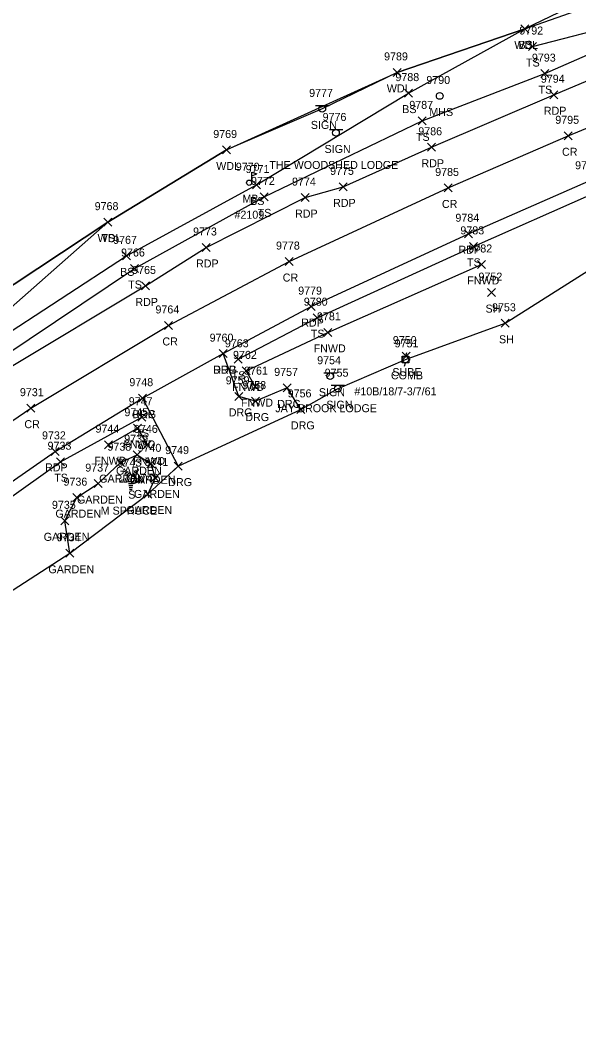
# Model space of a CAD drawing. Extents: x 1651685 to 1653558, y 889533 to 891085.
# Drawn here: x 1651859.6 to 1651999.4, y 889537.9 to 889789.1 of the extents above; entities that cross this region are included whole.
import ezdxf

# ---------------------------------------------------------------- set-up
doc = ezdxf.new("R2010")
doc.units = 0
for name, color, linetype in [('L_A', 7, 'Continuous'), ('L_C', 7, 'Continuous'), ('L_I', 7, 'Continuous'), ('L_TIC', 7, 'Continuous'), ('LAPB', 7, 'Continuous'), ('LAWA', 7, 'Continuous'), ('LELB', 7, 'Continuous'), ('LFNC', 7, 'Continuous'), ('LMB', 7, 'Continuous'), ('LSOGP', 7, 'Continuous'), ('LTC', 7, 'Continuous'), ('P_A', 7, 'Continuous'), ('P_I', 7, 'Continuous'), ('P_TIC', 7, 'Continuous'), ('PET', 7, 'Continuous'), ('PRC', 7, 'Continuous'), ('R_A', 7, 'Continuous'), ('R_I', 7, 'Continuous'), ('R_TIC', 7, 'Continuous'), ('RDG', 7, 'Continuous'), ('S_A', 7, 'Continuous'), ('S_C', 7, 'Continuous'), ('S_I', 7, 'Continuous'), ('SSGN', 7, 'Continuous'), ('U_A', 7, 'Continuous'), ('U_C', 7, 'Continuous'), ('U_I', 7, 'Continuous'), ('U_TIC', 7, 'Continuous'), ('UP', 7, 'Continuous'), ('USMH', 7, 'Continuous')]:
    doc.layers.add(name, color=color, linetype=linetype)

msp = doc.modelspace()

# ---------------------------------------------------------------- linework, layer by layer
at = {"layer": 'L_TIC'}
for points in [[(1651984.79, 889785.86), (1651986.79, 889787.86)], [(1651986.79, 889785.86), (1651984.79, 889787.86)], [(1651984.79, 889785.86), (1651986.79, 889787.86)], [(1651986.79, 889785.86), (1651984.79, 889787.86)], [(1651986.72, 889781.44), (1651988.72, 889783.44)], [(1651988.72, 889781.44), (1651986.72, 889783.44)], [(1651952.91, 889774.98), (1651954.91, 889776.98)], [(1651954.91, 889774.98), (1651952.91, 889776.98)], [(1651989.86, 889774.67), (1651991.86, 889776.67)], [(1651991.86, 889774.67), (1651989.86, 889776.67)], [(1651955.73, 889769.8), (1651957.73, 889771.8)], [(1651957.73, 889769.8), (1651955.73, 889771.8)], [(1651959.2, 889762.86), (1651961.2, 889764.86)], [(1651961.2, 889762.86), (1651959.2, 889764.86)], [(1651910.24, 889755.58), (1651912.24, 889757.58)], [(1651912.24, 889755.58), (1651910.24, 889757.58)], [(1651917.71, 889746.83), (1651919.71, 889748.83)], [(1651919.71, 889746.83), (1651917.71, 889748.83)], [(1651919.63, 889743.86), (1651921.63, 889745.86)], [(1651921.63, 889743.86), (1651919.63, 889745.86)], [(1651880.58, 889737.54), (1651882.58, 889739.54)], [(1651882.58, 889737.54), (1651880.58, 889739.54)], [(1651880.58, 889737.54), (1651882.58, 889739.54)], [(1651882.58, 889737.54), (1651880.58, 889739.54)], [(1651971.97, 889731.49), (1651973.97, 889733.49)], [(1651973.97, 889731.49), (1651971.97, 889733.49)], [(1651885.2, 889729.12), (1651887.2, 889731.12)], [(1651887.2, 889729.12), (1651885.2, 889731.12)], [(1651887.23, 889725.95), (1651889.23, 889727.95)], [(1651889.23, 889725.95), (1651887.23, 889727.95)], [(1651973.98, 889726.96), (1651975.98, 889728.96)], [(1651975.98, 889726.96), (1651973.98, 889728.96)], [(1651976.51, 889719.93), (1651978.51, 889721.93)], [(1651978.51, 889719.93), (1651976.51, 889721.93)], [(1651932.92, 889713.66), (1651934.92, 889715.66)], [(1651934.92, 889713.66), (1651932.92, 889715.66)], [(1651979.89, 889712.26), (1651981.89, 889714.26)], [(1651981.89, 889712.26), (1651979.89, 889714.26)], [(1651935.55, 889709.99), (1651937.55, 889711.99)], [(1651937.55, 889709.99), (1651935.55, 889711.99)], [(1651913.13, 889703.26), (1651915.13, 889705.26)], [(1651915.13, 889703.26), (1651913.13, 889705.26)], [(1651915.17, 889700.36), (1651917.17, 889702.36)], [(1651917.17, 889700.36), (1651915.17, 889702.36)], [(1651917.38, 889696.42), (1651919.38, 889698.42)], [(1651919.38, 889696.42), (1651917.38, 889698.42)], [(1651889.05, 889688.78), (1651891.05, 889690.78)], [(1651891.05, 889688.78), (1651889.05, 889690.78)], [(1651887.97, 889686.04), (1651889.97, 889688.04)], [(1651889.97, 889686.04), (1651887.97, 889688.04)], [(1651880.74, 889681.91), (1651882.74, 889683.91)], [(1651882.74, 889681.91), (1651880.74, 889683.91)], [(1651890.42, 889681.85), (1651892.42, 889683.85)], [(1651892.42, 889681.85), (1651890.42, 889683.85)], [(1651887.94, 889679.41), (1651889.94, 889681.41)], [(1651889.94, 889679.41), (1651887.94, 889681.41)], [(1651868.76, 889677.65), (1651870.76, 889679.65)], [(1651870.76, 889677.65), (1651868.76, 889679.65)], [(1651883.73, 889677.42), (1651885.73, 889679.42)], [(1651885.73, 889677.42), (1651883.73, 889679.42)], [(1651891.34, 889677.13), (1651893.34, 889679.13)], [(1651893.34, 889677.13), (1651891.34, 889679.13)], [(1651878.18, 889672.18), (1651880.18, 889674.18)], [(1651880.18, 889672.18), (1651878.18, 889674.18)], [(1651892.43, 889673.6), (1651894.43, 889675.6)], [(1651894.43, 889673.6), (1651892.43, 889675.6)], [(1651890.54, 889669.58), (1651892.54, 889671.58)], [(1651892.54, 889669.58), (1651890.54, 889671.58)], [(1651872.8, 889668.67), (1651874.8, 889670.67)], [(1651874.8, 889668.67), (1651872.8, 889670.67)], [(1651869.85, 889662.88), (1651871.85, 889664.88)], [(1651871.85, 889662.88), (1651869.85, 889664.88)], [(1651871.04, 889654.76), (1651873.04, 889656.76)], [(1651873.04, 889654.76), (1651871.04, 889656.76)]]:
    msp.add_lwpolyline(points, dxfattribs=at)
at = {"layer": 'LAPB'}
msp.add_lwpolyline([(1651872.04, 889655.76), (1651870.85, 889663.88), (1651873.8, 889669.67), (1651879.18, 889673.18), (1651884.73, 889678.42), (1651888.94, 889680.41), (1651892.34, 889678.13), (1651893.43, 889674.6), (1651891.54, 889670.58)], dxfattribs=at)
at = {"layer": 'LAWA'}
msp.add_lwpolyline([(1651786.37, 889684.82), (1651812.33, 889694.08), (1651846.44, 889715.35), (1651881.58, 889738.54), (1651911.24, 889756.58), (1651953.91, 889775.98), (1651985.79, 889786.86)], dxfattribs=at)
at = {"layer": 'LELB'}
for points in [[(1651783.6, 889675.23), (1651805.26, 889676.92), (1651818.09, 889682.86), (1651843.19, 889699.23), (1651855.35, 889704.9), (1651888.23, 889726.95), (1651920.63, 889744.86), (1651960.2, 889763.86), (1651990.86, 889775.67), (1652032.94, 889794.22), (1652064, 889805.11), (1652064.62, 889808.53), (1652063.28, 889810.56), (1652051.23, 889809.28), (1652039.29, 889812.4)], [(1651845.19, 889705.05), (1651852.98, 889708.46), (1651886.2, 889730.12), (1651918.71, 889747.83), (1651956.73, 889770.8), (1651985.79, 889786.86), (1652029.06, 889802.11), (1652062.87, 889807.04)], [(1651987.72, 889782.44), (1652032.94, 889794.22)], [(1651914.13, 889704.26), (1651933.92, 889714.66), (1651972.97, 889732.49), (1652002.78, 889745.6), (1652031.52, 889758.06)], [(1651784.29, 889679.75), (1651801.82, 889681.07), (1651814.94, 889688.3), (1651838.28, 889704.72), (1651850.92, 889711.55), (1651881.58, 889738.54)], [(1651735.5, 889537.87), (1651729.21, 889546.46), (1651724.72, 889554.06), (1651746.88, 889576.56), (1651775.98, 889603.69), (1651804.95, 889630.07), (1651836.41, 889654.97), (1651869.76, 889678.65), (1651890.05, 889689.78)]]:
    msp.add_lwpolyline(points, dxfattribs=at)
at = {"layer": 'LFNC'}
for points in [[(1651918.38, 889697.42), (1651916.17, 889701.36), (1651936.55, 889710.99), (1651974.98, 889727.96)], [(1651881.74, 889682.91), (1651888.97, 889687.04), (1651891.42, 889682.85)]]:
    msp.add_lwpolyline(points, dxfattribs=at)
at = {"layer": 'LMB'}
for p, q in [((1651917.56, 889748.41), (1651917.56, 889751.01)), ((1651917.56, 889751), (1651918.85, 889750.62)), ((1651917.56, 889750.11), (1651918.85, 889750.61)), ((1651916.91, 889748.4), (1651916.91, 889748.4))]:
    msp.add_line(p, q, dxfattribs=at)
msp.add_circle((1651916.91, 889748.4), 0.656, dxfattribs=at)
at = {"layer": 'LSOGP'}
for points in [[(1652028.35, 889807.39), (1651985.79, 889786.86), (1651953.91, 889775.99), (1651935.16, 889766.85), (1651911.24, 889756.58), (1651881.58, 889738.53), (1651846.44, 889715.35)], [(1651846.48, 889639.3), (1651872.04, 889655.76), (1651891.54, 889670.58), (1651899.18, 889677.56), (1651929.84, 889691.74), (1651939.03, 889696.91), (1651955.96, 889704.24), (1651980.89, 889713.26), (1652008.19, 889730.53)]]:
    msp.add_lwpolyline(points, dxfattribs=at)
at = {"layer": 'LTC'}
for p, q in [((1651885.47, 889676.64), (1651885.82, 889676.9)), ((1651885.68, 889676.18), (1651886.21, 889676.56)), ((1651888.5, 889676.53), (1651889.05, 889676.13)), ((1651888.87, 889676.88), (1651889.29, 889676.58)), ((1651884.5, 889673.92), (1651884.65, 889673.45)), ((1651884.96, 889674.14), (1651885.17, 889673.48)), ((1651885.41, 889674.35), (1651885.68, 889673.52)), ((1651885.87, 889674.57), (1651886.2, 889673.55)), ((1651885.89, 889675.71), (1651886.59, 889676.22)), ((1651886.1, 889675.24), (1651886.98, 889675.88)), ((1651886.32, 889674.79), (1651887.33, 889675.52)), ((1651886.32, 889674.79), (1651886.71, 889673.6)), ((1651887.33, 889675.52), (1651888.33, 889674.8)), ((1651887.75, 889675.84), (1651888.56, 889675.25)), ((1651888.33, 889674.8), (1651887.94, 889673.6)), ((1651888.13, 889676.18), (1651888.8, 889675.69)), ((1651888.77, 889674.53), (1651888.43, 889673.49)), ((1651889.21, 889674.28), (1651888.93, 889673.39)), ((1651889.66, 889674.03), (1651889.42, 889673.3)), ((1651887.94, 889673.6), (1651886.71, 889673.6)), ((1651887.9, 889673.1), (1651886.76, 889673.1)), ((1651887.82, 889672.6), (1651886.83, 889672.6)), ((1651887.73, 889672.1), (1651886.9, 889672.1)), ((1651887.65, 889671.6), (1651886.98, 889671.6)), ((1651890.1, 889673.78), (1651889.92, 889673.2))]:
    msp.add_line(p, q, dxfattribs=at)
at = {"layer": 'P_TIC'}
for points in [[(1651992.09, 889769.39), (1651994.09, 889771.39)], [(1651994.09, 889769.39), (1651992.09, 889771.39)], [(1651995.7, 889759.13), (1651997.7, 889761.13)], [(1651997.7, 889759.13), (1651995.7, 889761.13)], [(1651961.5, 889756.26), (1651963.5, 889758.26)], [(1651963.5, 889756.26), (1651961.5, 889758.26)], [(1651939.4, 889746.37), (1651941.4, 889748.37)], [(1651941.4, 889746.37), (1651939.4, 889748.37)], [(1651965.67, 889746.09), (1651967.67, 889748.09)], [(1651967.67, 889746.09), (1651965.67, 889748.09)], [(1651929.88, 889743.68), (1651931.88, 889745.68)], [(1651931.88, 889743.68), (1651929.88, 889745.68)], [(1651970.73, 889734.64), (1651972.73, 889736.64)], [(1651972.73, 889734.64), (1651970.73, 889736.64)], [(1651905.13, 889731.21), (1651907.13, 889733.21)], [(1651907.13, 889731.21), (1651905.13, 889733.21)], [(1651925.87, 889727.69), (1651927.87, 889729.69)], [(1651927.87, 889727.69), (1651925.87, 889729.69)], [(1651889.95, 889721.59), (1651891.95, 889723.59)], [(1651891.95, 889721.59), (1651889.95, 889723.59)], [(1651931.43, 889716.43), (1651933.43, 889718.43)], [(1651933.43, 889716.43), (1651931.43, 889718.43)], [(1651895.77, 889711.72), (1651897.77, 889713.72)], [(1651897.77, 889711.72), (1651895.77, 889713.72)], [(1651909.42, 889704.67), (1651911.42, 889706.67)], [(1651911.42, 889704.67), (1651909.42, 889706.67)], [(1651889.21, 889693.54), (1651891.21, 889695.54)], [(1651891.21, 889693.54), (1651889.21, 889695.54)], [(1651861.27, 889691.04), (1651863.27, 889693.04)], [(1651863.27, 889691.04), (1651861.27, 889693.04)], [(1651867.37, 889680.24), (1651869.37, 889682.24)], [(1651869.37, 889680.24), (1651867.37, 889682.24)]]:
    msp.add_lwpolyline(points, dxfattribs=at)
at = {"layer": 'PET'}
for points in [[(1651722.05, 889556.64), (1651743.79, 889579.05), (1651773.7, 889607.56), (1651801.99, 889632.45), (1651834.2, 889657.45), (1651868.37, 889681.24), (1651890.21, 889694.54), (1651910.42, 889705.67), (1651932.43, 889717.43), (1651971.73, 889735.64), (1652001.72, 889748.76), (1652035.56, 889763.08), (1652038.22, 889762.81), (1652052.59, 889768.76), (1652053.52, 889770.62), (1652076.54, 889779.88), (1652117.63, 889796.48), (1652147.54, 889808.21), (1652195.16, 889826.81), (1652233.48, 889842.54), (1652271.73, 889857.62), (1652310.07, 889873.86), (1652345.02, 889890.88)], [(1651704.37, 889572.46), (1651711.6, 889580), (1651712.47, 889582.84), (1651725.08, 889595.24), (1651758.1, 889627.66), (1651784.02, 889650.41), (1651820.32, 889679.04), (1651823.18, 889679.59), (1651856.55, 889701.98), (1651890.95, 889722.59), (1651906.13, 889732.21), (1651930.88, 889744.68), (1651940.4, 889747.37), (1651962.5, 889757.26), (1651993.09, 889770.39), (1652035.55, 889788.28)]]:
    msp.add_lwpolyline(points, dxfattribs=at)
at = {"layer": 'PRC'}
msp.add_lwpolyline([(1651712.82, 889564.71), (1651734.46, 889586.87), (1651766.27, 889617.28), (1651793.27, 889641.25), (1651826.92, 889667.91), (1651862.27, 889692.04), (1651896.77, 889712.72), (1651926.87, 889728.69), (1651966.67, 889747.09), (1651996.7, 889760.13), (1652040.05, 889778.15), (1652073.02, 889791.69), (1652113.32, 889807.56), (1652142.44, 889819.25), (1652190.37, 889838.24), (1652228.92, 889853.82), (1652266.92, 889869.48), (1652304.43, 889885.84), (1652339.13, 889902.36), (1652374.76, 889921.45)], dxfattribs=at)
at = {"layer": 'R_TIC'}
for points in [[(1651909.42, 889704.67), (1651911.42, 889706.67)], [(1651911.42, 889704.67), (1651909.42, 889706.67)], [(1651925.42, 889696.11), (1651927.42, 889698.11)], [(1651927.42, 889696.11), (1651925.42, 889698.11)], [(1651889.21, 889693.54), (1651891.21, 889695.54)], [(1651891.21, 889693.54), (1651889.21, 889695.54)], [(1651913.31, 889693.99), (1651915.31, 889695.99)], [(1651915.31, 889693.99), (1651913.31, 889695.99)], [(1651917.45, 889692.81), (1651919.45, 889694.81)], [(1651919.45, 889692.81), (1651917.45, 889694.81)], [(1651928.85, 889690.74), (1651930.85, 889692.74)], [(1651930.85, 889690.74), (1651928.85, 889692.74)], [(1651898.18, 889676.56), (1651900.18, 889678.56)], [(1651900.18, 889676.56), (1651898.18, 889678.56)]]:
    msp.add_lwpolyline(points, dxfattribs=at)
at = {"layer": 'RDG'}
for points in [[(1651929.85, 889691.74), (1651926.42, 889697.11), (1651918.45, 889693.81), (1651914.31, 889694.99), (1651910.42, 889705.67)], [(1651890.21, 889694.54), (1651899.18, 889677.56)]]:
    msp.add_lwpolyline(points, dxfattribs=at)
at = {"layer": 'SSGN'}
for p, q in [((1651933.53, 889767.71), (1651936.87, 889767.71)), ((1651935.18, 889766.87), (1651935.18, 889766.87)), ((1651936.96, 889761.7), (1651940.3, 889761.7)), ((1651938.61, 889760.87), (1651938.61, 889760.87)), ((1651935.54, 889700.89), (1651938.87, 889700.89)), ((1651937.19, 889700.05), (1651937.19, 889700.05)), ((1651937.41, 889697.76), (1651940.75, 889697.76)), ((1651939.06, 889696.93), (1651939.06, 889696.93))]:
    msp.add_line(p, q, dxfattribs=at)
for centre in [(1651935.18, 889766.87), (1651938.61, 889760.87), (1651937.19, 889700.05), (1651939.06, 889696.93)]:
    msp.add_circle(centre, 0.833, dxfattribs=at)
at = {"layer": 'U_TIC'}
for points in [[(1651955.17, 889704.06), (1651957.17, 889706.06)], [(1651957.17, 889704.06), (1651955.17, 889706.06)]]:
    msp.add_lwpolyline(points, dxfattribs=at)
at = {"layer": 'UP'}
for p, q in [((1651955.13, 889703.4), (1651955.13, 889705.07)), ((1651955.13, 889705.07), (1651956.8, 889705.07)), ((1651956.21, 889705.9), (1651955.96, 889705.07)), ((1651955.96, 889704.24), (1651955.96, 889704.24)), ((1651956.8, 889705.07), (1651956.8, 889703.4)), ((1651956.8, 889703.4), (1651955.13, 889703.4)), ((1651955.71, 889702.57), (1651955.96, 889703.4))]:
    msp.add_line(p, q, dxfattribs=at)
msp.add_circle((1651955.96, 889704.24), 0.833, dxfattribs=at)
at = {"layer": 'USMH'}
for p, q in [((1651964.54, 889770.08), (1651964.54, 889770.08)), ((1651965.37, 889770.08), (1651965.37, 889770.08))]:
    msp.add_line(p, q, dxfattribs=at)
msp.add_circle((1651964.54, 889770.08), 0.833, dxfattribs=at)

# ---------------------------------------------------------------- texts
at = {"layer": 'L_A'}
for s, p in [('WDL', (1651983.2, 889781.86)), ('BS', (1651984.23, 889781.86)), ('TS', (1651986.13, 889777.44)), ('WDL', (1651951.32, 889770.98)), ('TS', (1651989.27, 889770.67)), ('BS', (1651955.17, 889765.8)), ('TS', (1651958.61, 889758.86)), ('WDL', (1651908.66, 889751.58)), ('MB', (1651915.22, 889743.4)), ('BS', (1651917.15, 889742.83)), ('TS', (1651919.04, 889739.86)), ('WDL', (1651879, 889733.54)), ('TS', (1651879.99, 889733.54)), ('TS', (1651971.38, 889727.49)), ('BS', (1651884.64, 889725.12)), ('FNWD', (1651971.44, 889722.96)), ('TS', (1651886.64, 889721.95)), ('SH', (1651976, 889715.93)), ('TS', (1651932.32, 889709.66)), ('SH', (1651979.37, 889708.26)), ('FNWD', (1651933.02, 889705.99)), ('TS', (1651912.54, 889699.26)), ('FNWD', (1651912.63, 889696.36)), ('FNWD', (1651914.85, 889692.42)), ('TS', (1651888.46, 889684.78)), ('FNWD', (1651885.43, 889682.04)), ('FNWD', (1651878.2, 889677.91)), ('FNWD', (1651887.88, 889677.85)), ('GARDEN', (1651883.61, 889675.41)), ('TS', (1651868.17, 889673.65)), ('GARDEN', (1651879.4, 889673.42)), ('GARDEN', (1651887.01, 889673.13)), ('S', (1651886.66, 889669.43)), ('GARDEN', (1651888.1, 889669.6)), ('GARDEN', (1651873.85, 889668.18)), ('GARDEN', (1651868.46, 889664.67)), ('GARDEN', (1651886.21, 889665.58)), ('GARDEN', (1651865.52, 889658.88)), ('GARDEN', (1651866.71, 889650.76))]:
    msp.add_text(s, height=2, dxfattribs=at).set_placement(p)
at = {"layer": 'L_C'}
for s, p in [('#2109', (1651913.23, 889739.4)), ('M SPRUCE', (1651879.78, 889665.43))]:
    msp.add_text(s, height=2, dxfattribs=at).set_placement(p)
at = {"layer": 'L_I'}
for s, p in [('9792', (1651984.46, 889785.44)), ('9789', (1651950.64, 889778.98)), ('9793', (1651987.6, 889778.67)), ('9788', (1651953.47, 889773.8)), ('9787', (1651956.94, 889766.86)), ('9769', (1651907.92, 889759.58)), ('9770', (1651913.56, 889751.4)), ('9771', (1651916.02, 889750.83)), ('9772', (1651917.37, 889747.86)), ('9768', (1651878.27, 889741.54)), ('9768', (1651878.27, 889741.54)), ('9783', (1651969.71, 889735.49)), ('9767', (1651882.89, 889733.12)), ('9766', (1651884.87, 889729.95)), ('9782', (1651971.72, 889730.96)), ('9752', (1651974.25, 889723.93)), ('9780', (1651930.57, 889717.66)), ('9753', (1651977.63, 889716.26)), ('9781', (1651933.86, 889713.99)), ('9763', (1651910.83, 889707.26)), ('9762', (1651912.86, 889704.36)), ('9761', (1651915.64, 889700.42)), ('9747', (1651886.79, 889692.78)), ('9745', (1651885.71, 889690.04)), ('9744', (1651878.48, 889685.91)), ('9746', (1651888.1, 889685.85)), ('9739', (1651885.67, 889683.41)), ('9733', (1651866.5, 889681.65)), ('9738', (1651881.47, 889681.42)), ('9740', (1651888.99, 889681.13)), ('9743', (1651884.01, 889677.43)), ('9741', (1651890.74, 889677.6)), ('9737', (1651875.92, 889676.18)), ('9736', (1651870.48, 889672.67)), ('9742', (1651888.28, 889673.58)), ('9735', (1651867.59, 889666.88)), ('9734', (1651868.78, 889658.76))]:
    msp.add_text(s, height=2, dxfattribs=at).set_placement(p)
at = {"layer": 'LTC'}
msp.add_text('.', height=1.04, rotation=270, dxfattribs=at).set_placement((1651887.22, 889674.54))
at = {"layer": 'P_A'}
for s, p in [('RDP', (1651990.58, 889765.39)), ('CR', (1651995.13, 889755.13)), ('RDP', (1651959.99, 889752.26)), ('RDP', (1651937.89, 889742.37)), ('CR', (1651965.1, 889742.09)), ('RDP', (1651928.37, 889739.68)), ('RDP', (1651969.22, 889730.64)), ('RDP', (1651903.62, 889727.21)), ('CR', (1651925.3, 889723.69)), ('RDP', (1651888.44, 889717.59)), ('RDP', (1651929.92, 889712.43)), ('CR', (1651895.21, 889707.72)), ('RDP', (1651907.91, 889700.67)), ('RDP', (1651887.69, 889689.54)), ('CR', (1651860.7, 889687.04)), ('RDP', (1651865.86, 889676.24))]:
    msp.add_text(s, height=2, dxfattribs=at).set_placement(p)
at = {"layer": 'P_I'}
for s, p in [('9794', (1651989.83, 889773.39)), ('9795', (1651993.44, 889763.13)), ('9786', (1651959.19, 889760.26)), ('9775', (1651937.14, 889750.37)), ('9785', (1651963.41, 889750.09)), ('9796', (1651998.4, 889751.76)), ('9774', (1651927.62, 889747.68)), ('9784', (1651968.47, 889738.64)), ('9773', (1651902.87, 889735.21)), ('9778', (1651923.61, 889731.69)), ('9765', (1651887.65, 889725.59)), ('9779', (1651929.16, 889720.43)), ('9764', (1651893.47, 889715.72)), ('9760', (1651907.02, 889708.67)), ('9748', (1651886.95, 889697.54)), ('9731', (1651859.58, 889695.04)), ('9732', (1651865.11, 889684.24))]:
    msp.add_text(s, height=2, dxfattribs=at).set_placement(p)
at = {"layer": 'R_A'}
for p in [(1651907.91, 889700.67), (1651923.91, 889692.11), (1651887.69, 889689.54), (1651911.8, 889689.99), (1651915.94, 889688.81), (1651927.34, 889686.74), (1651896.67, 889672.56)]:
    msp.add_text('DRG', height=2, dxfattribs=at).set_placement(p)
at = {"layer": 'R_I'}
for s, p in [('9760', (1651907.02, 889708.67)), ('9757', (1651923.16, 889700.11)), ('9748', (1651886.95, 889697.54)), ('9759', (1651911.04, 889697.99)), ('9758', (1651915.19, 889696.81)), ('9756', (1651926.53, 889694.74)), ('9749', (1651895.91, 889680.56))]:
    msp.add_text(s, height=2, dxfattribs=at).set_placement(p)
at = {"layer": 'S_A'}
for p in [(1651932.32, 889761.85), (1651935.75, 889755.84), (1651934.33, 889695.03), (1651936.2, 889691.91)]:
    msp.add_text('SIGN', height=2, dxfattribs=at).set_placement(p)
at = {"layer": 'S_C'}
for s, p in [('THE WOODSHED LODGE', (1651921.94, 889751.84)), ('JAY BROOK LODGE', (1651923.44, 889691.03))]:
    msp.add_text(s, height=2, dxfattribs=at).set_placement(p)
at = {"layer": 'S_I'}
for s, p in [('9777', (1651931.9, 889769.85)), ('9776', (1651935.27, 889763.84)), ('9754', (1651933.91, 889703.03)), ('9755', (1651935.78, 889699.91))]:
    msp.add_text(s, height=2, dxfattribs=at).set_placement(p)
at = {"layer": 'U_A'}
for s, p in [('MHS', (1651961.96, 889765.08)), ('SUBE', (1651952.71, 889700.06)), ('COMB', (1651952.35, 889699.24))]:
    msp.add_text(s, height=2, dxfattribs=at).set_placement(p)
at = {"layer": 'U_C'}
msp.add_text('#10B/18/7-3/7/61', height=2, dxfattribs=at).set_placement((1651943.22, 889695.24))
at = {"layer": 'U_I'}
for s, p in [('9790', (1651961.2, 889773.08)), ('9750', (1651952.83, 889708.06)), ('9751', (1651953.27, 889707.24))]:
    msp.add_text(s, height=2, dxfattribs=at).set_placement(p)

doc.saveas('drawing.dxf')
